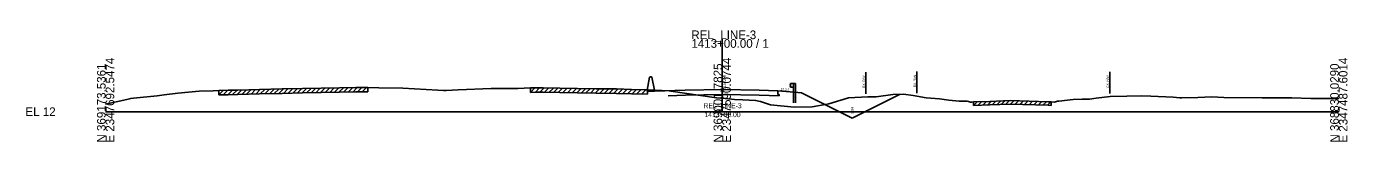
# Model space of a CAD drawing. Extents: x -26 to 2346329, y -10 to 370015.
# Drawn here: x 1974.3 to 2402.8, y 6490.3 to 6526.3 of the extents above; entities that cross this region are included whole.
import ezdxf

# ---------------------------------------------------------------- set-up
doc = ezdxf.new("R2010")
doc.units = 0
for name, color, linetype in [('RD_HC_Cl', 7, 'Continuous'), ('RD_HC_CL_Rel', 7, 'Continuous'), ('RD_HC_Data', 7, 'Continuous'), ('RD_HC_Data_Tic', 7, 'Continuous'), ('RD_HC_Data_Tic_Rel', 7, 'Continuous'), ('RD_HC_TX_Rel_Sta50', 7, 'Continuous'), ('RD_HC_TX_Sta50', 7, 'Continuous'), ('RD_PD_PatLn_526', 7, 'Continuous'), ('RD_PD_PatLn_LINE-A', 7, 'Continuous'), ('RD_PD_PatLn_LINE-B', 7, 'Continuous'), ('RD_PD_PatLn_REL_L-2118', 7, 'Continuous'), ('RD_PD_PatLn_REL_L-2523', 7, 'Continuous'), ('RD_PD_PatLn_Rel_LINE-3', 7, 'Continuous'), ('RD_TX_RoadID', 7, 'Continuous'), ('RD_TX_StaOff', 7, 'Continuous'), ('RD_XS_Pave', 7, 'Continuous')]:
    doc.layers.add(name, color=color, linetype=linetype)

msp = doc.modelspace()

# ---------------------------------------------------------------- linework, layer by layer
at = {"layer": 'RD_HC_Cl'}
for p, q in [((2200, 6500), (2200, 6523.5)), ((2000, 6500), (2200, 6500)), ((2200, 6500), (2400, 6500))]:
    msp.add_line(p, q, dxfattribs=at)
at = {"layer": 'RD_HC_Data'}
msp.add_lwpolyline([(2000, 6502.42), (2006.83, 6504), (2008.17, 6504.31), (2009.02, 6504.41), (2010.11, 6504.53), (2016.67, 6505.17), (2018.98, 6505.5), (2023.39, 6505.95), (2030.35, 6506.64), (2034.9, 6506.79), (2036.67, 6506.87), (2039.78, 6506.94), (2042.93, 6507.01), (2049.88, 6507.18), (2057.25, 6507.37), (2063.88, 6507.49), (2069.89, 6507.62), (2075.81, 6507.73), (2081.2, 6507.83), (2082.98, 6507.83), (2085.02, 6507.83), (2088.6, 6507.77), (2096.4, 6507.62), (2107.72, 6506.97), (2109.58, 6506.86), (2110.51, 6506.9), (2114.37, 6507.06), (2125, 6507.5), (2130.1, 6507.53), (2133.7, 6507.56), (2137.8, 6507.7), (2139.97, 6507.71), (2141.97, 6507.72), (2147.29, 6507.64), (2153.06, 6507.55), (2159.12, 6507.46), (2165.71, 6507.37), (2170.52, 6507.24), (2175.74, 6507.1), (2182.83, 6506.72), (2183.29, 6506.65), (2198.11, 6504.5), (2199.57, 6504.37), (2200, 6504.33), (2203.94, 6503.99), (2206.63, 6503.87), (2210.83, 6503.65), (2212.43, 6503.28), (2215.67, 6502.23), (2223.29, 6501.49), (2229.21, 6501.61), (2234.09, 6502.48), (2234.59, 6502.58), (2240.92, 6504.5), (2247.23, 6504.8), (2248.55, 6504.86), (2249.88, 6504.86), (2255.31, 6505.55), (2258.84, 6505.64), (2261.91, 6505.23), (2266.18, 6504.44), (2270.45, 6504.21), (2273.46, 6503.76), (2276.82, 6503.46), (2279.45, 6503.37), (2279.89, 6503.26), (2280.48, 6503.12), (2280.96, 6503.14), (2281.52, 6503.17), (2286.78, 6503.33), (2293.35, 6503.58), (2305.74, 6503.21), (2306.7, 6503.18), (2307.75, 6503.14), (2308.42, 6503.3), (2308.8, 6503.39), (2309.17, 6503.43), (2313.87, 6503.96), (2316.7, 6504.04), (2319.11, 6504.11), (2321.26, 6504.34), (2325.82, 6504.88), (2331.24, 6505.04), (2336.15, 6505.1), (2339.07, 6505.05), (2346.26, 6504.71), (2348.47, 6504.45), (2349.05, 6504.46), (2354.31, 6504.64), (2358.82, 6504.82), (2362.67, 6504.63), (2375.1, 6504.53), (2375.85, 6504.52), (2376.88, 6504.48), (2383.78, 6504.48), (2384.72, 6504.47), (2390.94, 6504.31), (2400, 6504.25)], dxfattribs=at)
at = {"layer": 'RD_HC_Data_Tic_Rel'}
for p, q in [((2225.75, 6506.14), (2242.15, 6497.94)), ((2242.15, 6497.94), (2257.48, 6505.6))]:
    msp.add_line(p, q, dxfattribs=at)
at = {"layer": 'RD_HC_TX_Rel_Sta50'}
for p, q in [((2188, 6507), (2200, 6507.24)), ((2200, 6507.24), (2212, 6507))]:
    msp.add_line(p, q, dxfattribs=at)
at = {"layer": 'RD_HC_TX_Sta50'}
for p, q in [((2036.67, 6505.43), (2038.14, 6506.9)), ((2036.67, 6505.43), (2036.67, 6506.87)), ((2036.67, 6505.43), (2039.78, 6505.5)), ((2038.17, 6505.47), (2039.64, 6506.94)), ((2039.67, 6505.5), (2041.14, 6506.97)), ((2039.78, 6505.5), (2042.93, 6505.57)), ((2041.17, 6505.53), (2042.64, 6507)), ((2042.67, 6505.57), (2044.14, 6507.04)), ((2042.93, 6505.57), (2049.88, 6505.74)), ((2044.17, 6505.6), (2045.64, 6507.08)), ((2045.67, 6505.64), (2047.14, 6507.11)), ((2047.17, 6505.67), (2048.64, 6507.15)), ((2048.67, 6505.71), (2050.14, 6507.18)), ((2049.88, 6505.74), (2057.25, 6505.93)), ((2050.17, 6505.75), (2051.65, 6507.22)), ((2051.67, 6505.79), (2053.15, 6507.26)), ((2053.17, 6505.82), (2054.65, 6507.3)), ((2054.67, 6505.86), (2056.15, 6507.34)), ((2056.17, 6505.9), (2057.64, 6507.37)), ((2057.25, 6505.93), (2063.88, 6506.06)), ((2057.67, 6505.94), (2059.14, 6507.4)), ((2059.17, 6505.97), (2060.64, 6507.43)), ((2060.67, 6505.99), (2062.14, 6507.46)), ((2062.17, 6506.02), (2063.64, 6507.49)), ((2063.67, 6506.05), (2065.14, 6507.52)), ((2063.88, 6506.06), (2069.89, 6506.18)), ((2065.17, 6506.08), (2066.64, 6507.55)), ((2066.67, 6506.12), (2068.14, 6507.58)), ((2068.17, 6506.15), (2069.64, 6507.62)), ((2069.67, 6506.18), (2071.14, 6507.64)), ((2069.89, 6506.18), (2075.81, 6506.3)), ((2071.17, 6506.21), (2072.64, 6507.67)), ((2072.67, 6506.24), (2074.14, 6507.7)), ((2074.17, 6506.27), (2075.64, 6507.73)), ((2075.67, 6506.29), (2077.13, 6507.76)), ((2075.81, 6506.3), (2081.2, 6506.4)), ((2077.17, 6506.32), (2078.63, 6507.79)), ((2078.67, 6506.35), (2080.13, 6507.81)), ((2080.17, 6506.38), (2081.63, 6507.83)), ((2081.2, 6506.4), (2082.98, 6506.4)), ((2081.67, 6506.4), (2083.11, 6507.83)), ((2082.98, 6506.4), (2085.02, 6506.4)), ((2083.17, 6506.4), (2084.61, 6507.83)), ((2085.02, 6507.83), (2085.02, 6506.4)), ((2137.8, 6506.26), (2139.25, 6507.71)), ((2137.8, 6506.26), (2137.8, 6507.7)), ((2137.8, 6506.26), (2139.97, 6506.28)), ((2139.3, 6506.27), (2140.74, 6507.71)), ((2139.97, 6506.28), (2141.97, 6506.28)), ((2140.8, 6506.28), (2142.24, 6507.71)), ((2141.97, 6506.28), (2147.29, 6506.2)), ((2142.3, 6506.28), (2143.72, 6507.69)), ((2143.8, 6506.25), (2145.22, 6507.67)), ((2145.3, 6506.23), (2146.72, 6507.64)), ((2146.8, 6506.21), (2148.22, 6507.62)), ((2147.29, 6506.2), (2153.06, 6506.11)), ((2148.3, 6506.18), (2149.72, 6507.6)), ((2149.8, 6506.16), (2151.22, 6507.58)), ((2151.3, 6506.14), (2152.72, 6507.56)), ((2152.8, 6506.12), (2154.22, 6507.53)), ((2153.06, 6506.11), (2159.12, 6506.02)), ((2154.3, 6506.1), (2155.72, 6507.51)), ((2155.8, 6506.07), (2157.22, 6507.49)), ((2157.3, 6506.05), (2158.72, 6507.47)), ((2158.8, 6506.03), (2160.22, 6507.45)), ((2159.12, 6506.02), (2165.71, 6505.93)), ((2160.3, 6506.01), (2161.72, 6507.43)), ((2161.8, 6505.99), (2163.22, 6507.4)), ((2163.3, 6505.97), (2164.72, 6507.38)), ((2164.8, 6505.95), (2166.21, 6507.36)), ((2165.71, 6505.93), (2170.52, 6505.8)), ((2166.3, 6505.92), (2167.7, 6507.32)), ((2167.8, 6505.88), (2169.2, 6507.28)), ((2169.3, 6505.84), (2170.7, 6507.24)), ((2170.52, 6505.8), (2175.74, 6505.67)), ((2170.8, 6505.8), (2172.2, 6507.2)), ((2172.3, 6505.76), (2173.7, 6507.16)), ((2173.8, 6505.72), (2175.2, 6507.12)), ((2175.74, 6507.1), (2175.74, 6505.67)), ((2281.52, 6502.03), (2282.7, 6503.21)), ((2281.52, 6502.03), (2281.52, 6503.17)), ((2281.52, 6502.03), (2286.78, 6502.19)), ((2283.02, 6502.07), (2284.2, 6503.25)), ((2284.52, 6502.12), (2285.7, 6503.3)), ((2286.02, 6502.16), (2287.2, 6503.34)), ((2286.78, 6502.19), (2293.35, 6502.44)), ((2287.52, 6502.21), (2288.71, 6503.4)), ((2289.02, 6502.27), (2290.21, 6503.46)), ((2290.52, 6502.33), (2291.71, 6503.52)), ((2292.02, 6502.39), (2293.21, 6503.58)), ((2293.35, 6502.44), (2305.74, 6502.07)), ((2293.52, 6502.43), (2294.63, 6503.54)), ((2295.02, 6502.39), (2296.13, 6503.5)), ((2296.52, 6502.34), (2297.63, 6503.45)), ((2298.02, 6502.3), (2299.13, 6503.41)), ((2299.52, 6502.25), (2300.63, 6503.36)), ((2301.02, 6502.21), (2302.13, 6503.32)), ((2302.52, 6502.16), (2303.63, 6503.27)), ((2304.02, 6502.12), (2305.13, 6503.23)), ((2305.52, 6502.07), (2306.63, 6503.19)), ((2305.74, 6502.07), (2306.7, 6502.04)), ((2306.7, 6503.18), (2306.7, 6502.04))]:
    msp.add_line(p, q, dxfattribs=at)
at = {"layer": 'RD_PD_PatLn_LINE-A'}
for p, q in [((2218, 6506.76), (2222, 6506.44)), ((2222, 6506.44), (2225.75, 6506.14))]:
    msp.add_line(p, q, dxfattribs=at)
at = {"layer": 'RD_PD_PatLn_LINE-B'}
for p, q in [((2182.49, 6505.14), (2188.05, 6505.37)), ((2188.05, 6505.37), (2200, 6505.61)), ((2200, 6505.61), (2211.97, 6505.37)), ((2218.5, 6505.11), (2211.97, 6505.37)), ((2218, 6506.76), (2218, 6505.62)), ((2218, 6505.62), (2218.5, 6505.58)), ((2218.5, 6505.58), (2218.5, 6505.11))]:
    msp.add_line(p, q, dxfattribs=at)
at = {"layer": 'RD_PD_PatLn_REL_L-2118'}
for p, q in [((2178, 6506.6), (2188, 6507)), ((2178, 6506.6), (2178, 6506.98)), ((2212, 6507), (2218, 6506.76))]:
    msp.add_line(p, q, dxfattribs=at)
at = {"layer": 'RD_PD_PatLn_Rel_LINE-3'}
for p, q in [((2176.46, 6511.15), (2175.67, 6507)), ((2176.83, 6511.27), (2176.58, 6511.27)), ((2177.09, 6511.27), (2176.83, 6511.27)), ((2178, 6507), (2177.21, 6511.15)), ((2175.67, 6507), (2175.67, 6506.6)), ((2175.67, 6506.6), (2176.83, 6506.6)), ((2176.83, 6506.6), (2178, 6506.6)), ((2178, 6506.6), (2178, 6507))]:
    msp.add_line(p, q, dxfattribs=at)
for centre, major_axis, start_param, end_param in [((2176.58, 6511.14), (0, -0.133), 3.141593, 4.607459), ((2177.09, 6511.14), (0, 0.133), 4.817319, 6.283185)]:
    msp.add_ellipse(centre, major_axis=major_axis, ratio=0.910156, start_param=start_param, end_param=end_param, dxfattribs=at)
at = {"layer": 'RD_TX_StaOff'}
for p, q in [((2222.17, 6509.03), (2222, 6508.83)), ((2222, 6508.83), (2222, 6508.78)), ((2222, 6508.78), (2222.17, 6508.58)), ((2222, 6508.26), (2222.17, 6508.46)), ((2222, 6508.21), (2222, 6508.26)), ((2222.17, 6508.01), (2222, 6508.21)), ((2222.17, 6507.93), (2222.17, 6509.1)), ((2222.17, 6509.1), (2223.08, 6509.1)), ((2222.17, 6507.93), (2223.08, 6507.93)), ((2223.08, 6509.1), (2223.08, 6506.36)), ((2223.08, 6509.1), (2223.75, 6509.1)), ((2223.08, 6502.89), (2223.08, 6506.36)), ((2223.75, 6509.1), (2223.75, 6506.3)), ((2223.75, 6506.3), (2223.75, 6502.89))]:
    msp.add_line(p, q, dxfattribs=at)
at = {"layer": 'RD_XS_Pave'}
for p, q in [((2246.58, 6505.77), (2246.58, 6512.77)), ((2263.09, 6506.01), (2263.09, 6513.01)), ((2325.68, 6505.87), (2325.68, 6512.87))]:
    msp.add_line(p, q, dxfattribs=at)

# ---------------------------------------------------------------- texts
at = {"layer": 'RD_HC_Cl'}
for s, p in [('1413+00.00 / 1', (2190, 6520.7)), ('REL_LINE-3', (2190, 6523.5)), ('EL 12', (1974, 6498.6))]:
    msp.add_text(s, height=2.8, dxfattribs=at).set_placement(p)
for s, p in [('N 369173.5361', (2000, 6490)), ('E 2347692.5474', (2002.8, 6490)), ('N 369001.7825', (2200, 6490)), ('E 2347590.0744', (2202.8, 6490)), ('N 368830.0290', (2400, 6490)), ('E 2347487.6014', (2402.8, 6490))]:
    msp.add_text(s, height=2.8, rotation=90, dxfattribs=at).set_placement(p)
at = {"layer": 'RD_HC_CL_Rel'}
msp.add_text('12.5:1', height=0.75, rotation=355.4261, dxfattribs=at).set_placement((2218.88, 6506.98))
at = {"layer": 'RD_HC_Data_Tic'}
msp.add_text('16.33', height=1, rotation=90, dxfattribs=at).set_placement((2200.5, 6504.33))
at = {"layer": 'RD_PD_PatLn_526'}
for s, p in [('REL_LINE-3', (2193.9, 6501.14)), ('1413+00.00', (2194.23, 6498.24))]:
    msp.add_text(s, height=1.6, dxfattribs=at).set_placement(p)
at = {"layer": 'RD_PD_PatLn_REL_L-2523'}
msp.add_text('9.94', height=0.8, rotation=90, dxfattribs=at).set_placement((2242.61, 6499.38))
at = {"layer": 'RD_TX_RoadID'}
msp.add_text(' 19.24', height=1.2, rotation=90, dxfattribs=at).set_placement((2201.2, 6507.24))
at = {"layer": 'RD_XS_Pave'}
for p in [(2246.33, 6507.72), (2262.83, 6507.96), (2325.42, 6507.82)]:
    msp.add_text('EX. R/W ', height=0.75, rotation=90, dxfattribs=at).set_placement(p)

doc.saveas('drawing.dxf')
